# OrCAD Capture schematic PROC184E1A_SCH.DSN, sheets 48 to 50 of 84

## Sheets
48 51. JTAG MIPI60 CONN: size C; title: JTAG MIPI60 CONNECTOR; note: PROC184_SCH
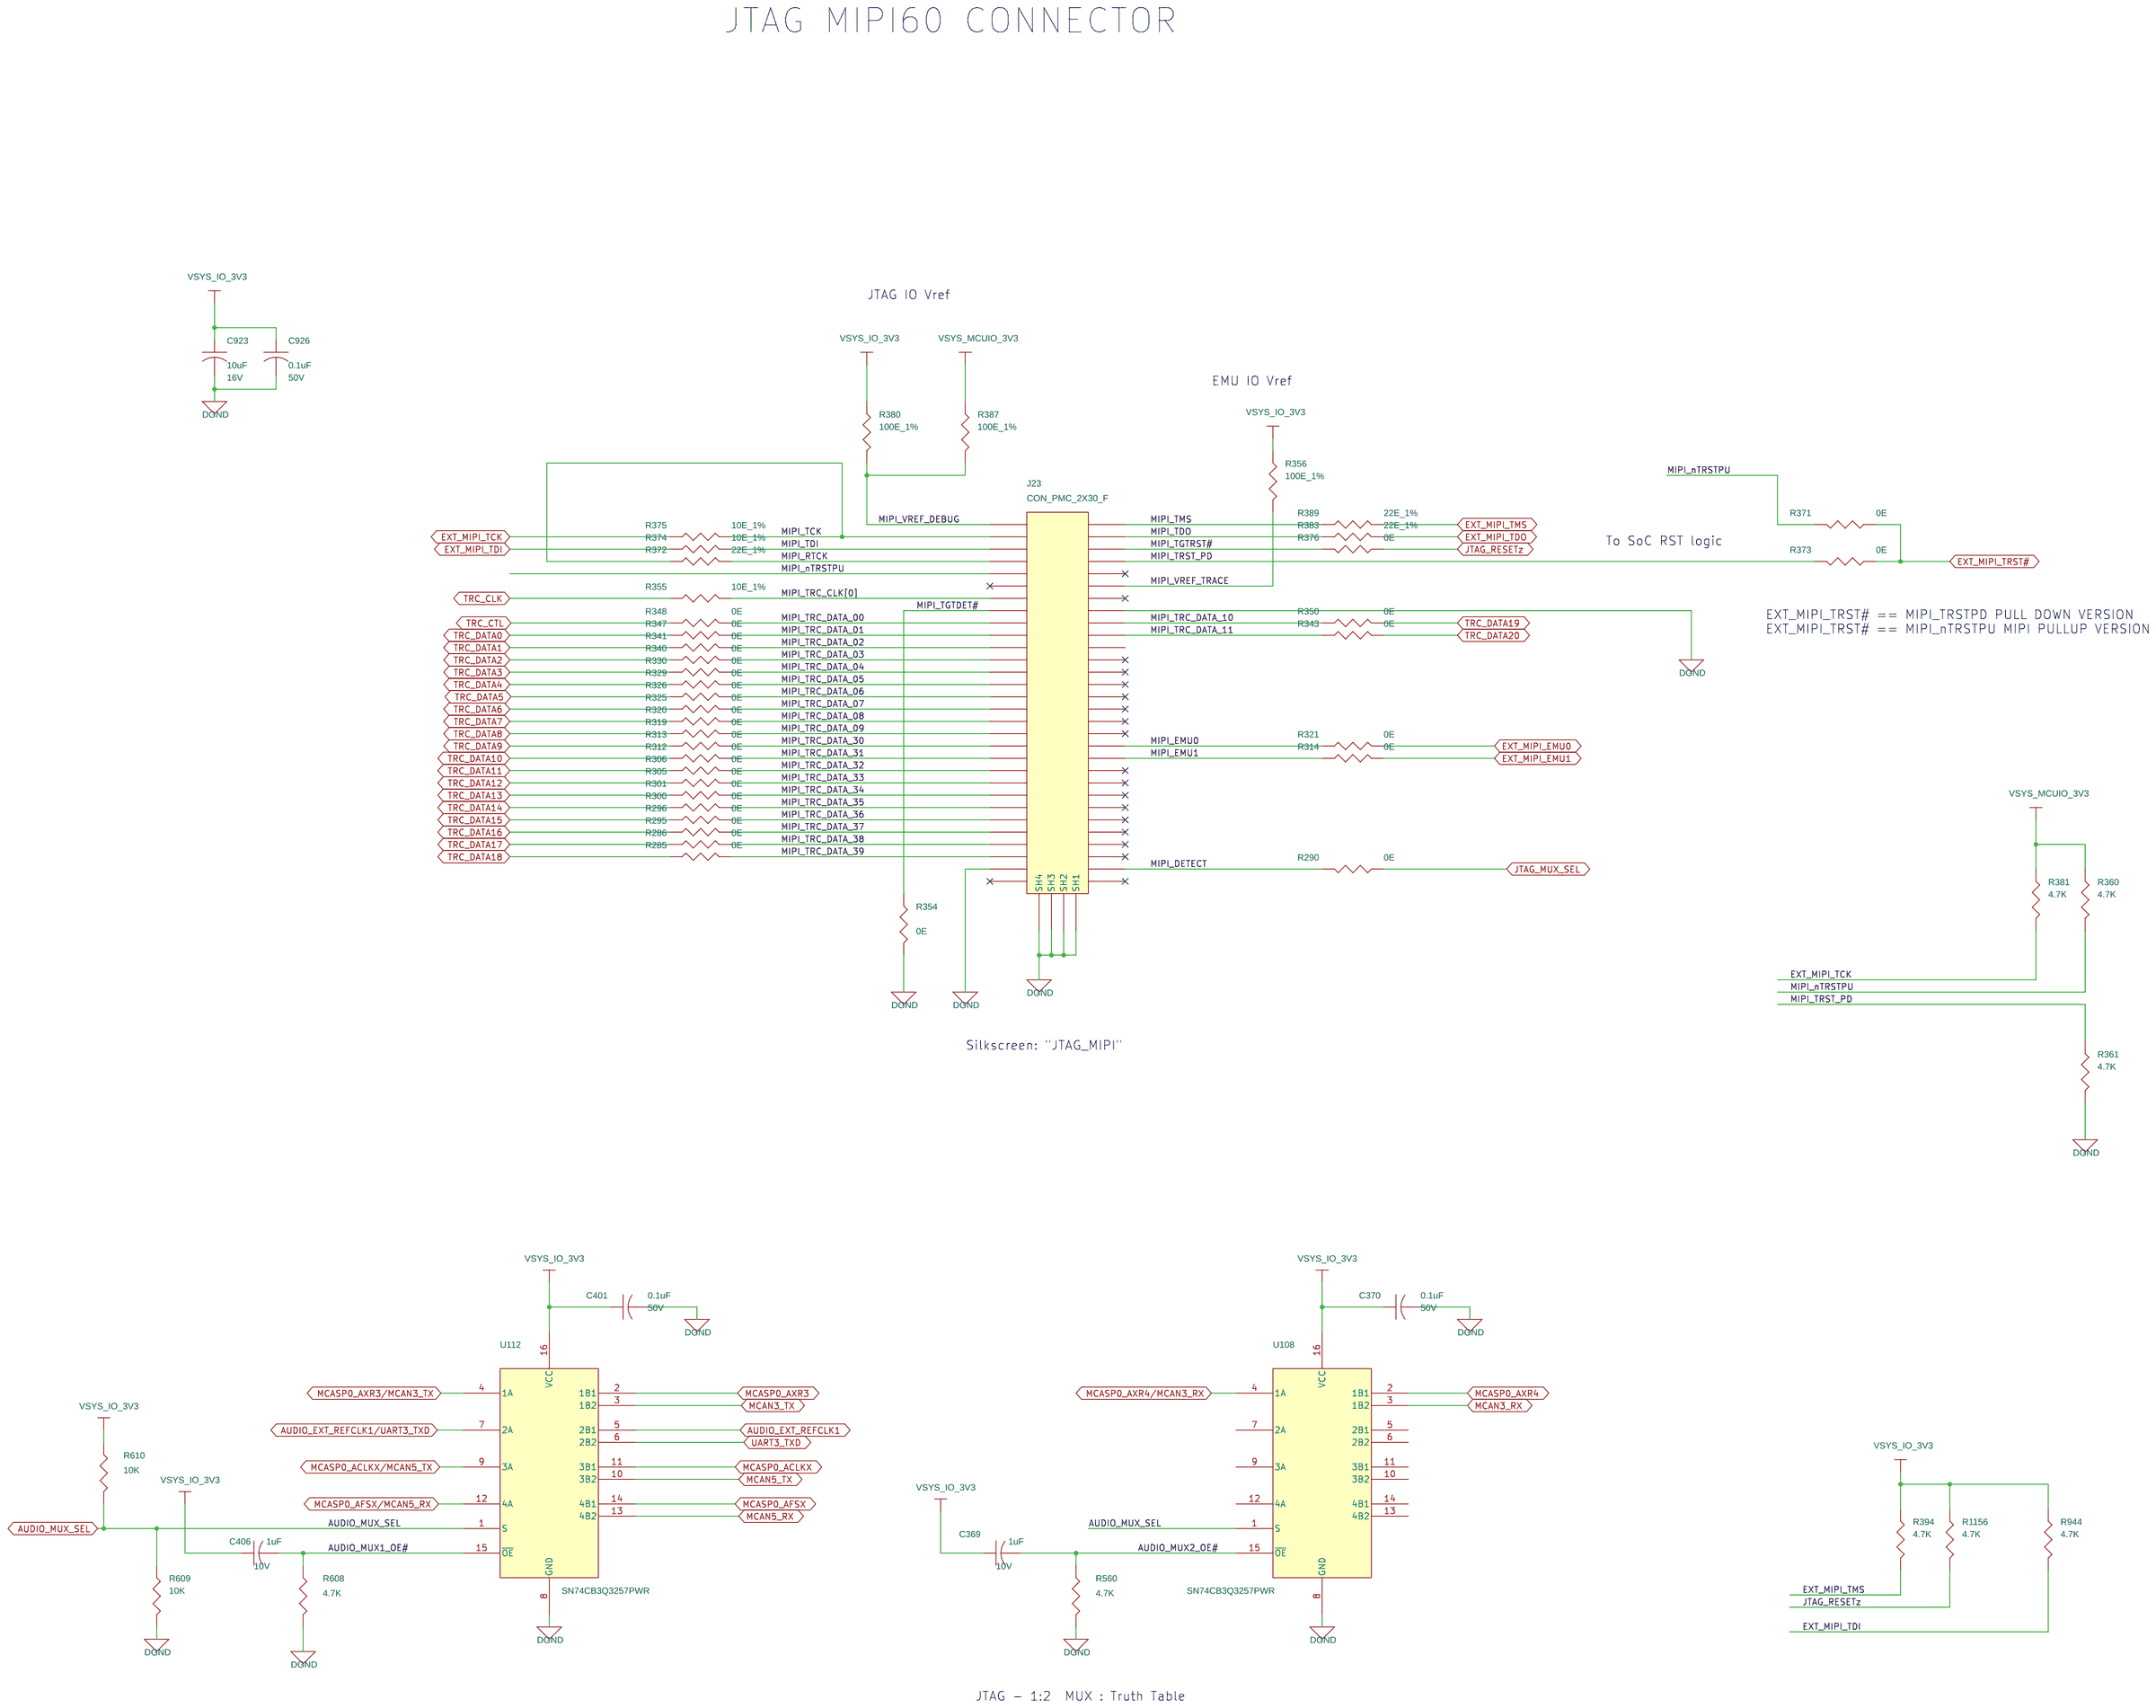
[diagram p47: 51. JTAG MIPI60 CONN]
49 53. CAN TRANSCEIVERS #1: size C; title: CAN TRANSCEIVERS #1; note: PROC184_SCH
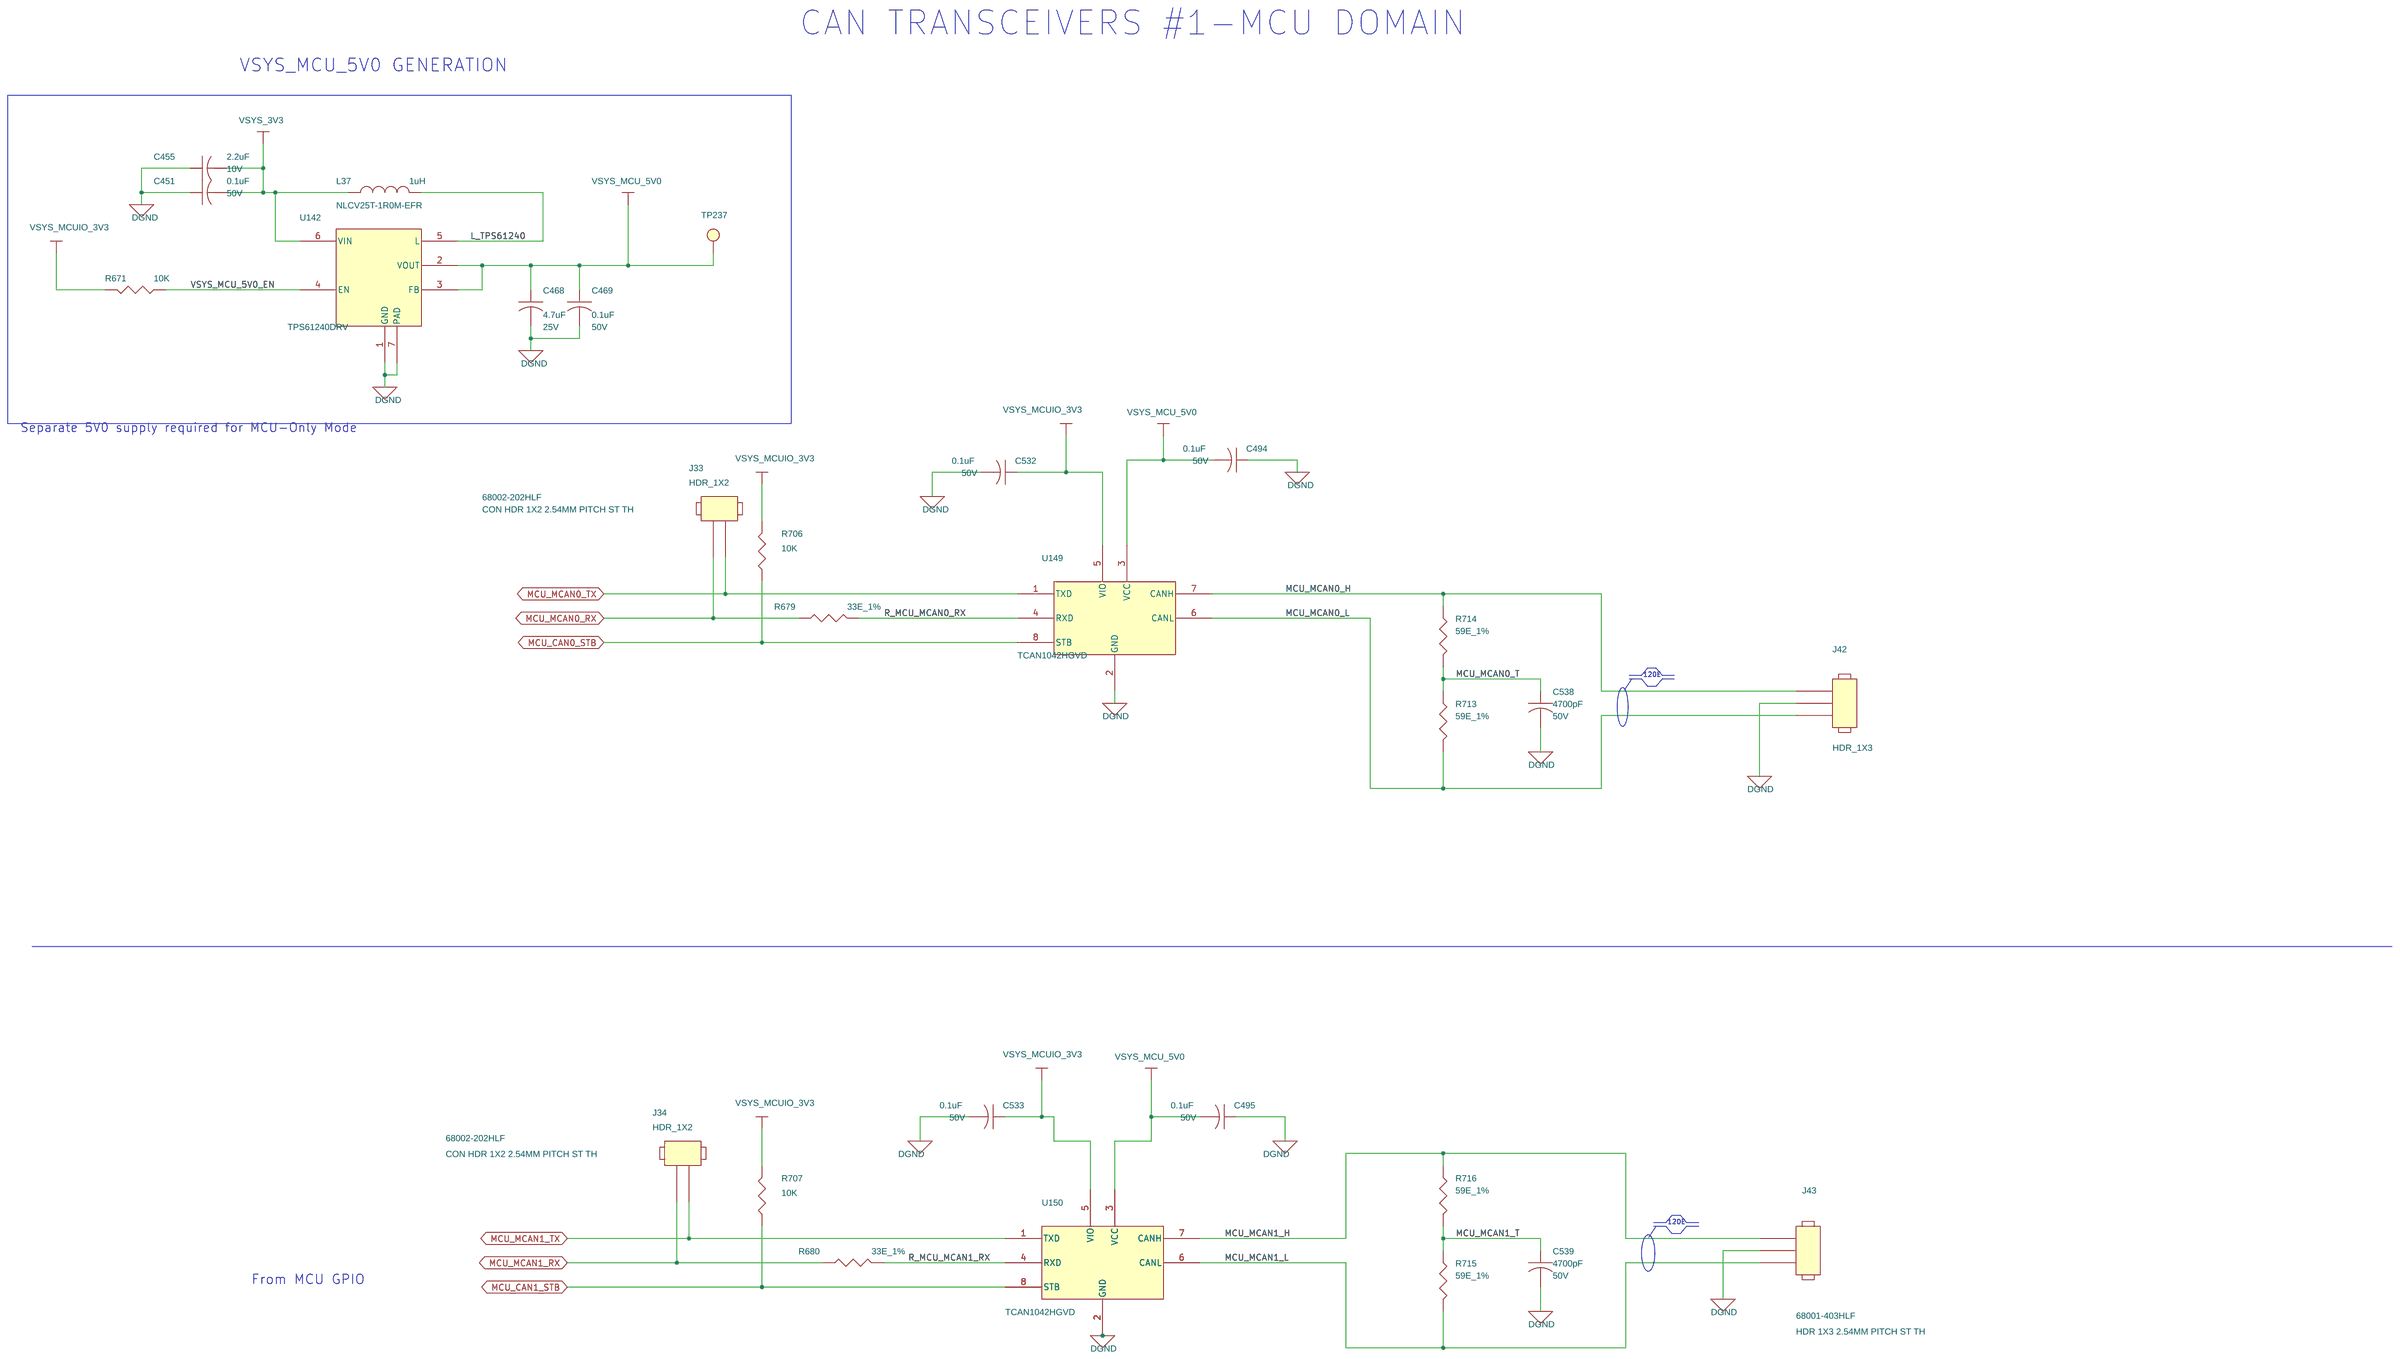
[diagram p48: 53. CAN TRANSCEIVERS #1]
50 54. CAN TRANSCEIVERS #2: size C; title: CAN TRANSCEIVER #2; note: PROC184_SCH
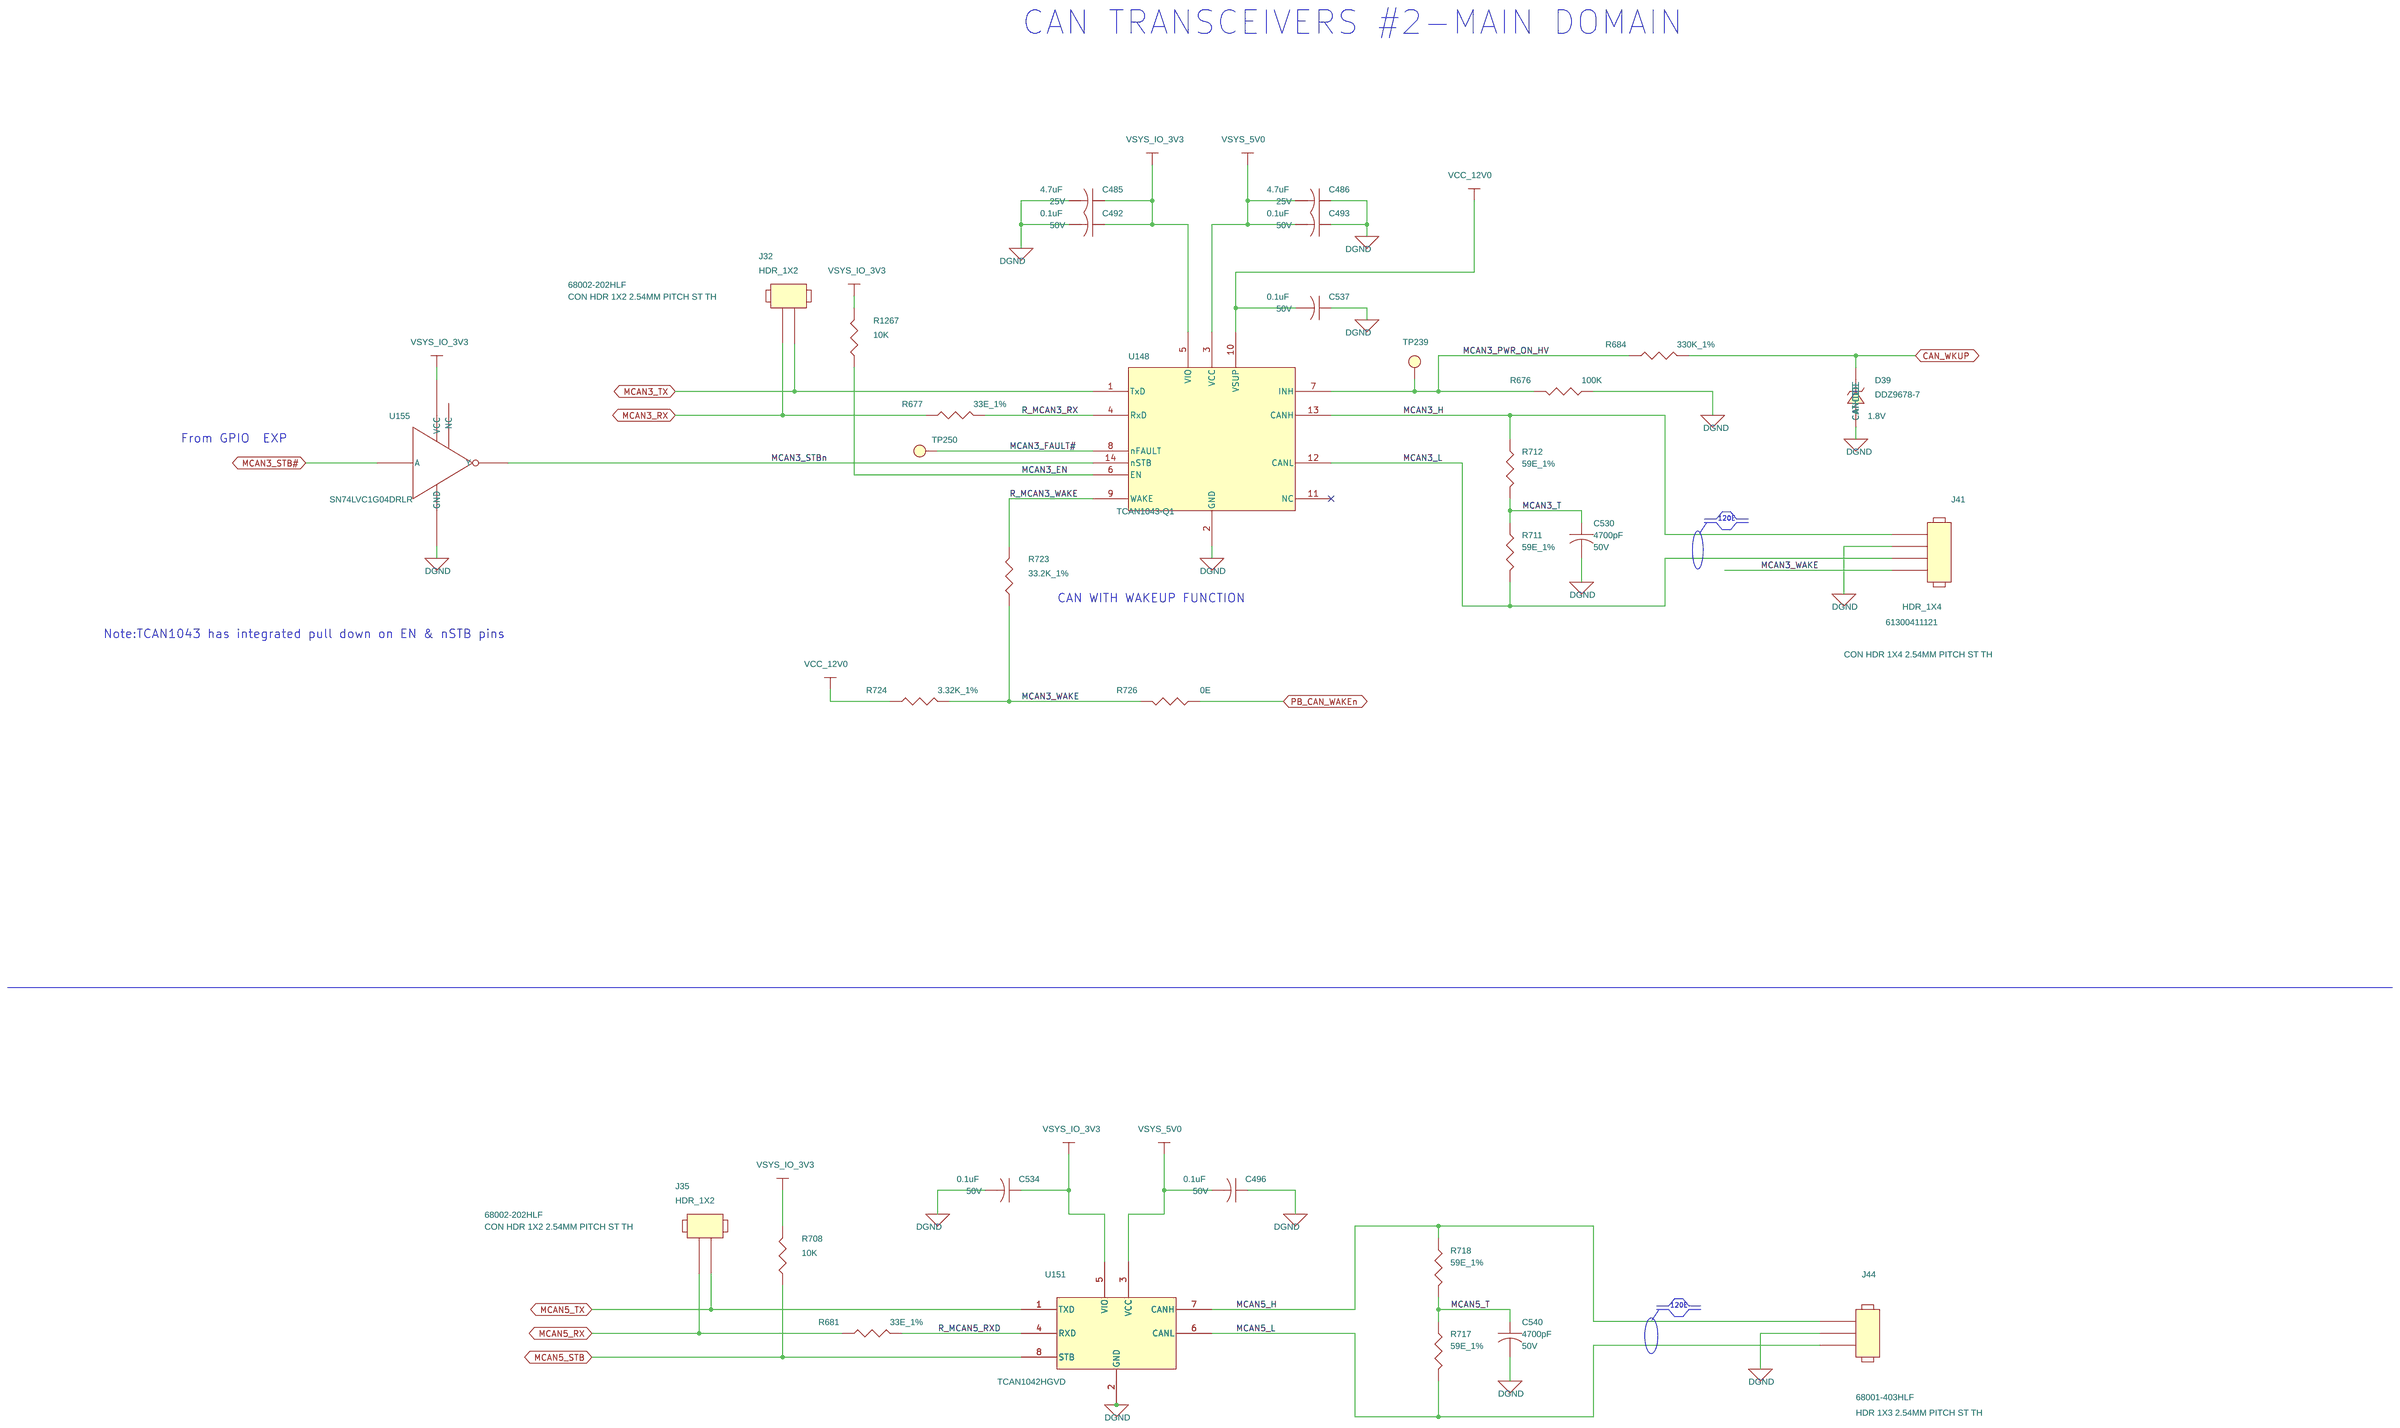
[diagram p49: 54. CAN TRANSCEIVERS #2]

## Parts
sheet 51. JTAG MIPI60 CONN
C369  1uF  [CAP0402_0-75]
C370  0.1uF  [CAP0402_0-75]
C401  0.1uF  [CAP0402_0-75]
C406  1uF  [CAP0402_0-75]
C923  10uF  [CAP0805_1-5]
C926  0.1uF  [CAP0402_0-75]
J23  CON_PMC_2X30_F  [CON_PMC2X30_QSH-030-01-D-A_S_S_S_3-3]
R285  0E  [RES0402_0-5]
R286  0E  [RES0402_0-5]
R290  0E  [RES0402_0-5]
R295  0E  [RES0402_0-5]
R296  0E  [RES0402_0-5]
R300  0E  [RES0402_0-5]
R301  0E  [RES0402_0-5]
R305  0E  [RES0402_0-5]
R306  0E  [RES0402_0-5]
R312  0E  [RES0402_0-5]
R313  0E  [RES0402_0-5]
R314  0E  [RES0402_0-5]
R319  0E  [RES0402_0-5]
R320  0E  [RES0402_0-5]
R321  0E  [RES0402_0-5]
R325  0E  [RES0402_0-5]
R326  0E  [RES0402_0-5]
R329  0E  [RES0402_0-5]
R330  0E  [RES0402_0-5]
R340  0E  [RES0402_0-5]
R341  0E  [RES0402_0-5]
R343  0E  [RES0402_0-5]
R347  0E  [RES0402_0-5]
R348  0E  [RES0402_0-5]
R350  0E  [RES0402_0-5]
R354  0E  [RES0402_0-5]
R355  10E_1%  [RES0402_0-5]
R356  100E_1%  [RES0402_0-5]
R360  4.7K  [RES0402_0-5]
R361  4.7K  [RES0402_0-5]
R371  0E  [RES0402_0-5]
R372  22E_1%  [RES0402_0-5]
R373  0E  [RES0402_0-5]
R374  10E_1%  [RES0402_0-5]
R375  10E_1%  [RES0402_0-5]
R376  0E  [RES0402_0-5]
R380  100E_1%  [RES0402_0-5]
R381  4.7K  [RES0402_0-5]
R383  22E_1%  [RES0402_0-5]
R387  100E_1%  [RES0402_0-5]
R389  22E_1%  [RES0402_0-5]
R394  4.7K  [RES0402_0-5]
R560  4.7K  [RES0402_0-5]
R608  4.7K  [RES0402_0-5]
R609  10K  [RES0402_0-5]
R610  10K  [RES0402_0-5]
R944  4.7K  [RES0402_0-5]
R1156  4.7K  [RES0402_0-5]
U108  SN74CB3Q3257PWR  [TSSOP16_25-59_205X180]
U112  SN74CB3Q3257PWR  [TSSOP16_25-59_205X180]
sheet 53. CAN TRANSCEIVERS #1
C451  0.1uF  [CAP0402_0-75]
C455  2.2uF  [CAP0402_0-75]
C468  4.7uF  [CAP0603_1]
C469  0.1uF  [CAP0402_0-75]
C494  0.1uF  [CAP0402_0-75]
C495  0.1uF  [CAP0402_0-75]
C532  0.1uF  [CAP0402_0-75]
C533  0.1uF  [CAP0402_0-75]
C538  4700pF  [CAP0402_0-75]
C539  4700pF  [CAP0402_0-75]
J33  HDR_1X2  [HDR_1X2_68002-202_S_T_8-6]
J34  HDR_1X2  [HDR_1X2_68002-202_S_T_8-6]
J42  HDR_1X3  [HDR_3X1_100_S_T]
J43  HDR_1X3  [HDR_3X1_100_S_T]
L37  1uH  [IND_NLCV25T-EFR_110X80_SMD_1-9]
R671  10K  [RES0402_0-5]
R679  33E_1%  [RES0402_0-5]
R680  33E_1%  [RES0402_0-5]
R706  10K  [RES0402_0-5]
R707  10K  [RES0402_0-5]
R713  59E_1%  [RES0402_0-5]
R714  59E_1%  [RES0402_0-5]
R715  59E_1%  [RES0402_0-5]
R716  59E_1%  [RES0402_0-5]
TP237  TP30_SMD  [TP30_SMD]
U142  TPS61240DRV  [SON6_25-59_85X85]
U149  TCAN1042HGVD  [SOIC8_1-8]
U150  TCAN1042HGVD  [SOIC8_1-8]
sheet 54. CAN TRANSCEIVERS #2
C485  4.7uF  [CAP0603_1]
C486  4.7uF  [CAP0603_1]
C492  0.1uF  [CAP0402_0-75]
C493  0.1uF  [CAP0402_0-75]
C496  0.1uF  [CAP0402_0-75]
C530  4700pF  [CAP0402_0-75]
C534  0.1uF  [CAP0402_0-75]
C537  0.1uF  [CAP0402_0-75]
C540  4700pF  [CAP0402_0-75]
D39  DDZ9678-7  [DIO_SOD123_1-5]
J32  HDR_1X2  [HDR_1X2_68002-202_S_T_8-6]
J35  HDR_1X2  [HDR_1X2_68002-202_S_T_8-6]
J41  HDR_1X4  [HDR_1X4_61300411121_S_T_8-6]
J44  HDR_1X3  [HDR_3X1_100_S_T]
R676  100K  [RES0402_0-5]
R677  33E_1%  [RES0402_0-5]
R681  33E_1%  [RES0402_0-5]
R684  330K_1%  [RES0402_0-5]
R708  10K  [RES0402_0-5]
R711  59E_1%  [RES0402_0-5]
R712  59E_1%  [RES0402_0-5]
R717  59E_1%  [RES0402_0-5]
R718  59E_1%  [RES0402_0-5]
R723  33.2K_1%  [RES0402_0-5]
R724  3.32K_1%  [RES0402_0-5]
R726  0E  [RES0402_0-5]
R1267  10K  [RES0402_0-5]
TP239  TP30_SMD  [TP30_SMD]
TP250  TP30_SMD  [TP30_SMD]
U148  TCAN1043-Q1  [SOIC14_1-8]
U151  TCAN1042HGVD  [SOIC8_1-8]
U155  SN74LVC1G04DRLR  [SOT553-5]

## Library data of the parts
C369 C406 = CAP: CAP CERAMIC 1uF 10V 10% X7S AUTO 0402; Automotive Alternate_mfr_name: TAIYO YUDEN; Automotive Alternate_mfr_part_number: EMK105BJ105KVHF; Chkd/date: MANIRAJA/100918; Crtd /date: ALVY/100918; Custom_Duty: 15%; Customs_HS_Code: 85322990; Direct Alternate_mfr_name: YAGEO AMERICA; Direct Alternate_mfr_part_number: CC0402KRX5R7BB105; Distributor_name: DIGIKEY; Distributor_part_number: 490-13409-1-ND; Footprint Path: Y:\MIS_DATABASE\Library\ALTIUM_TOOL\PCB_FOOTPRINTS\Altium_Footprint_Lib.PcbLib; Height: 0.70MM; Library Path: Y:\MIS_DATABASE\Library\ALTIUM_TOOL\SCHEMATICS_PARTS\MS_DISCRETE_Library.schlib; Manufacturer: TDK CORPORATION; Mfr_name: MURATA; Mfr_part_number: GCM155C71A105KE38D; Mistral Part No: 120018090021-R; Package: 0402; Part_type: CAPACITORS\CERAMIC; Project: SMART-M_SCRIPTALK_PB; RoHS: RoHS; Temperature: -55°C+125°C; Tolerance: 10%; Voltage: 10V; Wattage: NA; Weight: 6mg; Datasheet: Y:\MIS_DATABASE\DATASHEETS\CAPACITORS\MURATA-GCM-SER.PDF
C370 C401 C451 C469 C492-C496 C532-C534 C537 C926 = CAP: CAP CERAMIC 0.1uF 50V 10% X7R 0402; Automotive Alternate_mfr_name: TDK; Automotive Alternate_mfr_part_number: CGA2B3X7R1H104K050BB; Chkd/date: MANIRAJA/261020; Crtd /date: ALVY/211020; Custom_Duty: 15%; Customs_HS_Code: 85322990; Direct Alternate_mfr_name: TDK; Direct Alternate_mfr_part_number: C1005X7R1H104K050BE; Distributor_name: DIGIKEY; Distributor_part_number: 490-10700-1-ND; Footprint Path: Y:\MIS_DATABASE\Library\ALTIUM_TOOL\PCB_FOOTPRINTS\Altium_Footprint_Lib.PcbLib; Height: 0.55MM; Library Path: Y:\MIS_DATABASE\Library\ALTIUM_TOOL\SCHEMATICS_PARTS\MS_DISCRETE_Library.schlib; Manufacturer: MURATA; Mfr_name: MURATA; Mfr_part_number: GRM155R71H104KE14D; Mistral Part No: 120011100014-R; Package: 0402; Part_type: CAPACITORS\CERAMIC; Project: J7_CP; RoHS: RoHS; Temperature: -55°C+125°C; Tolerance: 10%; Voltage: 50V; Wattage: NA; Weight: 3.1mg; Datasheet: Y:\MIS_DATABASE\DATASHEETS\CAPACITORS\GRM155R71H104KE14.PDF
C923 = CAP: CAP CERAMIC 10uF 16V 10% X5R 0805; Automotive Alternate_mfr_name: TDK; Automotive Alternate_mfr_part_number: CGA4J1X7S1C106K125AC; Chkd/date: SHREESHAIL/220506; Crtd /date: MAZHAR/150506; Custom_Duty: 15%; Customs_HS_Code: 85322990; Direct Alternate_mfr_name: TDK; Direct Alternate_mfr_part_number: C2012X7S1C106K125AC; Distributor_name: DIGIKEY; Distributor_part_number: 490-3886-1-ND; Footprint Path: Y:\MIS_DATABASE\Library\ALTIUM_TOOL\PCB_FOOTPRINTS\Altium_Footprint_Lib.PcbLib; Height: 1.35MM; Library Path: Y:\MIS_DATABASE\Library\ALTIUM_TOOL\SCHEMATICS_PARTS\MS_DISCRETE_Library.schlib; Manufacturer: MURATA; Mfr_name: MURATA; Mfr_part_number: GRM21BR61C106KE15L; Mistral Part No: 120009030205-R; Package: 0805; Part_type: CAPACITORS\CERAMIC; Project: VOCERA; RoHS: RoHS; Temperature: -55°C+85°C; Tolerance: 10%; Voltage: 16V; Wattage: NA; Weight: 9.5mg; Datasheet: Y:\MIS_DATABASE\DATASHEETS\CAPACITORS\MURATA-GXX-SER_NOV17.PDF
J23 = CON_PMC_30X2_F_4SH: CON PMC 2X30 0.50MM PITCH FEMALE ST SMD; Chkd/date: MANIRAJA/310818; Crtd /date: ALVY/310818; Custom_Duty: 24%; Customs_HS_Code: 85369090; Distributor_name: DIGIKEY; Distributor_part_number: SAM13215CT-ND; Footprint Path: Y:\MIS_DATABASE\Library\ALTIUM_TOOL\PCB_FOOTPRINTS\Altium_Footprint_Lib.PcbLib; Height: 3.25MM; Library Path: Y:\MIS_DATABASE\Library\ALTIUM_TOOL\SCHEMATICS_PARTS\MS_CONNECTOR_Library.schlib; Manufacturer: SAMTEC; Mfr_name: SAMTEC; Mfr_part_number: QSH-030-01-L-D-A-K-TR; Mistral Part No: 150018080018-R; Package: SMD; Part_type: CONNECTOR\PMC; Project: 77GHzFR; RoHS: RoHS; Temperature: -55°C+125°C; Tolerance: NA; Voltage: NA; Wattage: NA; Weight: NA; Datasheet: Y:\MIS_DATABASE\DATASHEETS\CONNECTORS\QSH.PDF
R285 R286 R290 R295 R296 R300 R301 R305 R306 R312-R314 R319-R321 R325 R326 R329 R330 R340 R341 R343 R347 R348 R350 R354 R373 R376 R726 = RESISTOR: RES 0E 1/10W JUMPER 0402; Chkd/date: VASANTHA/061216; Crtd /date: NAVEED/201014; Custom_Duty: 15%; Customs_HS_Code: 85332119; Distributor_name: DIGIKEY; Distributor_part_number: P0.0JCT-ND; Footprint Path: Y:\MIS_DATABASE\Library\ALTIUM_TOOL\PCB_FOOTPRINTS\Altium_Footprint_Lib.PcbLib; Height: 0.40MM; IBISSP_MODLES: VALUE REPEATING 2 TIME; Library Path: Y:\MIS_DATABASE\Library\ALTIUM_TOOL\SCHEMATICS_PARTS\MS_DISCRETE_Library.schlib; Manufacturer: PANASONIC-ECG; Mfr_name: PANASONIC-ECG; Mfr_part_number: ERJ-2GE0R00X; Mistral Part No: 110018030052-R; Package: 0402; Part_type: RESISTORS\FIXED; Project: AEGIS POM; RoHS: RoHS; Temperature: -55°C+155°C; Tolerance: NA; Voltage: NA; Wattage: 1/10W; Weight: 0.8mg; Datasheet: Y:\MIS_DATABASE\DATASHEETS\RESISTORS\PAN-ERJSER_NOV17.PDF
R355 R374 R375 = RESISTOR: RES 10E 1/10W 1% 0402; Chkd/date: VASANTHA/201216; Crtd /date: MAZHAR/120505; Custom_Duty: 15%; Customs_HS_Code: 85332119; Distributor_name: DIGIKEY; Distributor_part_number: P10.0LCT-ND; Footprint Path: Y:\MIS_DATABASE\Library\ALTIUM_TOOL\PCB_FOOTPRINTS\Altium_Footprint_Lib.PcbLib; Height: 0.40MM; Library Path: Y:\MIS_DATABASE\Library\ALTIUM_TOOL\SCHEMATICS_PARTS\MS_DISCRETE_Library.schlib; Manufacturer: PANASONIC-ECG; Mfr_name: PANASONIC-ECG; Mfr_part_number: ERJ-2RKF10R0X; Mistral Part No: 110009030203-R; Package: 0402; Part_type: RESISTORS\FIXED; Project: CTP02_REVA_BASE; RoHS: RoHS; Temperature: -55°C+155°C; Tolerance: 1%; Voltage: NA; Wattage: 1/10W; Weight: 0.8mg; Datasheet: Y:\MIS_DATABASE\DATASHEETS\RESISTORS\PAN-ERJSER_NOV17.PDF
R356 R380 R387 = RESISTOR: RES 100E 1/10W 1% 0402; Chkd/date: MANIRAJA/130617; Crtd /date: JEBRAN/040715; Custom_Duty: 15%; Customs_HS_Code: 85332119; Distributor_name: DIGIKEY; Distributor_part_number: P100LCT-ND; Footprint Path: Y:\MIS_DATABASE\Library\ALTIUM_TOOL\PCB_FOOTPRINTS\Altium_Footprint_Lib.PcbLib; Height: 0.40MM; Library Path: Y:\MIS_DATABASE\Library\ALTIUM_TOOL\SCHEMATICS_PARTS\MS_DISCRETE_Library.schlib; Manufacturer: PANASONIC-ECG; Mfr_name: PANASONIC-ECG; Mfr_part_number: ERJ-2RKF1000X; Mistral Part No: 110018020036-R; Package: 0402; Part_type: RESISTORS\FIXED; Project: CYPHY_FVB; RoHS: RoHS; Temperature: -55°C+155°C; Tolerance: 1%; Voltage: NA; Wattage: 1/10W; Weight: 0.8mg; Datasheet: Y:\MIS_DATABASE\DATASHEETS\RESISTORS\PAN-ERJSER_NOV17.PDF
R360 R361 R381 R394 R560 R608 R944 R1156 = RESISTOR: RES 4.7K 1/16W 5% 0402; Chkd/date: VASANTHA/130516; Crtd /date: VASANTHA/130516; Custom_Duty: 15%; Customs_HS_Code: 85332119; Distributor_name: DIGIKEY; Distributor_part_number: 311-4.7KJRCT-ND; Footprint Path: Y:\MIS_DATABASE\Library\ALTIUM_TOOL\PCB_FOOTPRINTS\Altium_Footprint_Lib.PcbLib; Height: 0.40MM; Library Path: Y:\MIS_DATABASE\Library\ALTIUM_TOOL\SCHEMATICS_PARTS\MS_DISCRETE_Library.schlib; Manufacturer: YAGEO AMERICA; Mfr_name: YAGEO AMERICA; Mfr_part_number: RC0402JR-074K7L; Mistral Part No: 110011060001-R; Package: 0402; Part_type: RESISTORS\FIXED; Project: TMDXCSK368; RoHS: RoHS; Temperature: -55°C+155°C; Tolerance: 5%; Voltage: NA; Wattage: 1/16W; Weight: 0.65mg; Datasheet: Y:\MIS_DATABASE\DATASHEETS\RESISTORS\RCXXXXL-SER_MAR18.PDF
R371 = RESISTOR: RES 0E 1/10W JUMPER 0402; Assembly_Instruction: DNI; Chkd/date: VASANTHA/061216; Crtd /date: NAVEED/201014; Custom_Duty: 15%; Customs_HS_Code: 85332119; Distributor_name: DIGIKEY; Distributor_part_number: P0.0JCT-ND; Footprint Path: Y:\MIS_DATABASE\Library\ALTIUM_TOOL\PCB_FOOTPRINTS\Altium_Footprint_Lib.PcbLib; Height: 0.40MM; IBISSP_MODLES: VALUE REPEATING 2 TIME; Library Path: Y:\MIS_DATABASE\Library\ALTIUM_TOOL\SCHEMATICS_PARTS\MS_DISCRETE_Library.schlib; Manufacturer: PANASONIC-ECG; Mfr_name: PANASONIC-ECG; Mfr_part_number: ERJ-2GE0R00X; Mistral Part No: 110018030052-R; Package: 0402; Part_type: RESISTORS\FIXED; Project: AEGIS POM; RoHS: RoHS; Temperature: -55°C+155°C; Tolerance: NA; Voltage: NA; Wattage: 1/10W; Weight: 0.8mg; Datasheet: Y:\MIS_DATABASE\DATASHEETS\RESISTORS\PAN-ERJSER_NOV17.PDF
R372 R383 R389 = RESISTOR: RES 22E 1/16W 1% 0402; Chkd/date: SUHAS/290910; Crtd /date: MAZHAR/090909; Cust_part_number: 4700-80047E; Custom_Duty: 15%; Customs_HS_Code: 85332119; Distributor_name: DIGIKEY; Distributor_part_number: 311-22.0LRCT-ND; Footprint Path: Y:\MIS_DATABASE\Library\ALTIUM_TOOL\PCB_FOOTPRINTS\Altium_Footprint_Lib.PcbLib; Height: 0.40MM; Library Path: Y:\MIS_DATABASE\Library\ALTIUM_TOOL\SCHEMATICS_PARTS\MS_DISCRETE_Library.schlib; Manufacturer: YAGEO AMERICA; Mfr_name: YAGEO AMERICA; Mfr_part_number: RC0402FR-0722RL; Mistral Part No: 110009090004-R; Package: 0402; Part_type: RESISTORS\FIXED; Project: VMEFMCD; RoHS: RoHS; Temperature: -55°C+155°C; Tolerance: 1%; Voltage: NA; Wattage: 1/16W; Weight: 0.65mg; Datasheet: Y:\MIS_DATABASE\DATASHEETS\RESISTORS\RCXXXXL-SER_MAR18.PDF
R609 = RESISTOR: RES 10K 1/16W 5% 0402; Assembly_Instruction: DNI; Chkd/date: VASANTHA/061216; Crtd /date: MAZHAR/230805; Custom_Duty: 15%; Customs_HS_Code: 85332119; Distributor_name: DIGIKEY; Distributor_part_number: 311-10KJRCT-ND; Footprint Path: Y:\MIS_DATABASE\Library\ALTIUM_TOOL\PCB_FOOTPRINTS\Altium_Footprint_Lib.PcbLib; Height: 0.40MM; Library Path: Y:\MIS_DATABASE\Library\ALTIUM_TOOL\SCHEMATICS_PARTS\MS_DISCRETE_Library.schlib; Manufacturer: YAGEO AMERICA; Mfr_name: YAGEO AMERICA; Mfr_part_number: RC0402JR-0710KL; Mistral Part No: 110011060021-R; Package: 0402; Part_type: RESISTORS\FIXED; Project: HSE; RoHS: RoHS; Temperature: -55°C+155°C; Tolerance: 5%; Voltage: NA; Wattage: 1/16W; Weight: 0.65mg; Datasheet: Y:\MIS_DATABASE\DATASHEETS\RESISTORS\RCXXXXL-SER_MAR18.PDF
R610 R671 R706-R708 R1267 = RESISTOR: RES 10K 1/16W 5% 0402; Chkd/date: VASANTHA/061216; Crtd /date: MAZHAR/230805; Custom_Duty: 15%; Customs_HS_Code: 85332119; Distributor_name: DIGIKEY; Distributor_part_number: 311-10KJRCT-ND; Footprint Path: Y:\MIS_DATABASE\Library\ALTIUM_TOOL\PCB_FOOTPRINTS\Altium_Footprint_Lib.PcbLib; Height: 0.40MM; Library Path: Y:\MIS_DATABASE\Library\ALTIUM_TOOL\SCHEMATICS_PARTS\MS_DISCRETE_Library.schlib; Manufacturer: YAGEO AMERICA; Mfr_name: YAGEO AMERICA; Mfr_part_number: RC0402JR-0710KL; Mistral Part No: 110011060021-R; Package: 0402; Part_type: RESISTORS\FIXED; Project: HSE; RoHS: RoHS; Temperature: -55°C+155°C; Tolerance: 5%; Voltage: NA; Wattage: 1/16W; Weight: 0.65mg; Datasheet: Y:\MIS_DATABASE\DATASHEETS\RESISTORS\RCXXXXL-SER_MAR18.PDF
U108 U112 = SN74CB3Q3257PWR_TSSOP16: IC 4BIT 1-OF-2 FET MULTIPLEXER/DEMULTIPLEXER TSSOP16; Chkd/date: SUHAS/251010; Crtd /date: USMAN/060109; Custom_Duty: 15%; Customs_HS_Code: 85423100; Distributor_name: DIGIKEY; Distributor_part_number: 296-19138-1-ND; Height: 1.20MM; Manufacturer: TEXAS INSTRUMENTS; Mfr_name: TEXAS INSTRUMENTS; Mistral Part No: 141009030117-R; Package: TSSOP16; Part_type: ICS\DIGITAL\COMBINATIONAL; Project: OMAP_EVM; RoHS: Sb/ Br FREE; Temperature: -40°C+85°C; Datasheet: Y:\MIS_DATABASE\DATASHEETS\ICS\DIGITAL\COMBINATIONAL\SN74CB3Q3257.PDF
C455 = CAP: CAP CERAMIC 2.2uF 10V 10% X5R 0402; Automotive Alternate_mfr_name: TAIYO YUDEN; Automotive Alternate_mfr_part_number: LMK105ABJ225MVHF; Chkd/date: MANIRAJA/251120; Crtd /date: ALVY/241120; Custom_Duty: 15%; Customs_HS_Code: 85322990; Direct Alternate_mfr_name: TDK; Direct Alternate_mfr_part_number: C1005X5R1A225K050BC; Distributor_name: MOUSER; Distributor_part_number: 81-GRM155R61A225K01D; Footprint Path: Y:\MIS_DATABASE\Library\ALTIUM_TOOL\PCB_FOOTPRINTS\Altium_Footprint_Lib.PcbLib; Height: 0.55MM; Library Path: Y:\MIS_DATABASE\Library\ALTIUM_TOOL\SCHEMATICS_PARTS\MS_DISCRETE_Library.schlib; Manufacturer: MURATA; Mfr_name: MURATA; Mfr_part_number: GRM155R61A225KE01D; Mistral Part No: 120011100038-R; Package: 0402; Part_type: CAPACITORS\CERAMIC; Project: PLCC_DIGITAL BRD PROTO; RoHS: RoHS; Temperature: -55°C+85°C; Tolerance: 10%; Voltage: 10V; Wattage: NA; Weight: 1.6mg; Datasheet: Y:\MIS_DATABASE\DATASHEETS\CAPACITORS\MURATA-GXX-SER_NOV17.PDF
C468 C485 C486 = CAP: CAP CERAMIC 4.7uF 25V 10% X6S 0603; Chkd/date: MANIRAJA/241018; Crtd /date: ALVY/241018; Custom_Duty: 15%; Customs_HS_Code: 85322990; Direct Alternate_mfr_name: MURATA; Direct Alternate_mfr_part_number: GRM188C81E475ME11D; Distributor_name: DIGIKEY; Distributor_part_number: 490-7199-1-ND; Footprint Path: Y:\MIS_DATABASE\Library\ALTIUM_TOOL\PCB_FOOTPRINTS\Altium_Footprint_Lib.PcbLib; Height: 1.00MM; Library Path: Y:\MIS_DATABASE\Library\ALTIUM_TOOL\SCHEMATICS_PARTS\MS_DISCRETE_Library.schlib; Manufacturer: MURATA; Mfr_name: MURATA; Mfr_part_number: GRM188C81E475KE11D; Mistral Part No: 120018100056-R; Package: 0603; Part_type: CAPACITORS\CERAMIC; Project: TI_J7ES_EVM_CP; RoHS: RoHS; Temperature: -55°C+105°C; Tolerance: 10%; Voltage: 25V; Wattage: NA; Weight: 6.3mg; Datasheet: Y:\MIS_DATABASE\DATASHEETS\CAPACITORS\GRM188C81E475KE11D.PDF
C530 C538-C540 = CAP: CAP CERAMIC 4700pF 50V 5% X7R 0402; Automotive Alternate_mfr_name: TDK; Automotive Alternate_mfr_part_number: CGA2B2X7R1H472K050BA; Chkd/date: MANIRAJA/070619; Crtd /date: MANIRAJA/070619; Custom_Duty: 15%; Customs_HS_Code: 85322990; Direct Alternate_mfr_name: SAMSUNG; Direct Alternate_mfr_part_number: CL05B472KB5NNNC; Distributor_name: DIGIKEY; Distributor_part_number: 478-5767-1-ND; Footprint Path: Y:\MIS_DATABASE\Library\ALTIUM_TOOL\PCB_FOOTPRINTS\Altium_Footprint_Lib.PcbLib; Height: 0.56MM; Library Path: Y:\MIS_DATABASE\Library\ALTIUM_TOOL\SCHEMATICS_PARTS\MS_DISCRETE_Library.schlib; Manufacturer: AVX CORPORATION; Mfr_name: AVX CORPORATION; Mfr_part_number: 04025C472JAT2A; Mistral Part No: 120013090022-R; Package: 0402; Part_type: CAPACITORS\CERAMIC; Project: J7ES_SOM_DUAL-LEO_PMIC; RoHS: RoHS; Temperature: -55°C+125°C; Tolerance: 5%; Voltage: 50V; Wattage: NA; Weight: 0.65mg; Datasheet: Y:\MIS_DATABASE\DATASHEETS\CAPACITORS\AVX_MLC.PDF
J32-J35 = HEADER_2X1: CON HDR 1X2 2.54MM PITCH ST TH; Chkd/date: MANIRAJA/190118; Crtd /date: ALVY/190118; Custom_Duty: 24%; Customs_HS_Code: 85369090; Distributor_name: DIGIKEY; Distributor_part_number: 68002-202HLF-ND; Height: 8.58MM; Manufacturer: AMPHENOL; Mfr_name: AMPHENOL; Mfr_part_number: 68002-202HLF; Mistral Part No: 150018010012-R; Package: THRU HOLE; Part_type: CONNECTOR\HEADERS; Project: TI_SVB_MAXWELL_DUT; RoHS: RoHS; Temperature: NA; Tolerance: NA; Voltage: NA; Wattage: NA; Weight: NA; Datasheet: Y:\MIS_DATABASE\DATASHEETS\CONNECTORS\68002.PDF
J42-J44 = HEADER_3X1: HDR 1X3 2.54MM PITCH ST TH; Chkd/date: VASANTHA/290616; Crtd /date: VASANTHA/290616; Custom_Duty: 15%; Customs_HS_Code: 85322990; Distributor_name: DIGIKEY; Distributor_part_number: 609-3471-ND; Height: 8.58MM; Manufacturer: FCI; Mfr_name: FCI; Mfr_part_number: 68001-403HLF; Mistral Part No: 150016060025-R; Package: THRU-HOLE; Part_type: CONNECTOR\HEADERS; Project: IKEYP; RoHS: RoHS; Temperature: -40°C+105°C; Tolerance: NA; Voltage: NA; Wattage: NA; Weight: NA; Datasheet: Y:\MIS_DATABASE\DATASHEETS\CONNECTORS\68000.PDF
L37 = INDUCTOR: IND POWER 1uH 1A 20% SMD; Automotive Alternate_mfr_name: TDK; Automotive Alternate_mfr_part_number: NLCV25T-1R0M-EFRD; Chkd/date: MANIRAJA/161118; Crtd /date: ALVY/161118; Custom_Duty: 24%; Customs_HS_Code: 85369090; Direct Alternate_mfr_name: TDK; Direct Alternate_mfr_part_number: NLCV25T-1R0M-EFR; Distributor_name: DIGIKEY; Distributor_part_number: 445-17087-1-ND; Footprint Path: Y:\MIS_DATABASE\Library\ALTIUM_TOOL\PCB_FOOTPRINTS\Altium_Footprint_Lib.PcbLib; Height: 1.90MM; Library Path: Y:\MIS_DATABASE\Library\ALTIUM_TOOL\SCHEMATICS_PARTS\MS_DISCRETE_Library.schlib; Manufacturer: TDK CORPORATION; Mfr_name: TDK CORPORATION; Mfr_part_number: NLCV25T-1R0M-EFR; Mistral Part No: 130018110021-R; Package: SMD; Project: TI_J7ES_EVM_CP; RoHS: RoHS; Temperature: -40°C+125°C; Tolerance: 20%; Voltage: NA; Wattage: NA; Weight: 25mg; Datasheet: Y:\MIS_DATABASE\DATASHEETS\DISCRETES\INDUCTORS\NLCV25T-EFR.PDF
R677 R679-R681 = RESISTOR: RES 33E 1/10W 1% 0402; Chkd/date: VASANTHA/061216; Crtd /date: JEBRAN/171114; Custom_Duty: 15%; Customs_HS_Code: 85332119; Distributor_name: DIGIKEY; Distributor_part_number: P33.0LCT-ND; Footprint Path: Y:\MIS_DATABASE\Library\ALTIUM_TOOL\PCB_FOOTPRINTS\Altium_Footprint_Lib.PcbLib; Height: 0.40MM; Library Path: Y:\MIS_DATABASE\Library\ALTIUM_TOOL\SCHEMATICS_PARTS\MS_DISCRETE_Library.schlib; Manufacturer: PANASONIC-ECG; Mfr_name: PANASONIC-ECG; Mfr_part_number: ERJ-2RKF33R0X; Mistral Part No: 110014110006-R; Package: 0402; Part_type: RESISTORS\FIXED; Project: ZK BIOMETRIC; RoHS: RoHS; Temperature: -55°C+155°C; Tolerance: 1%; Voltage: NA; Wattage: 1/10W; Weight: 0.8mg; Datasheet: Y:\MIS_DATABASE\DATASHEETS\RESISTORS\PAN-ERJSER_NOV17.PDF
R711-R718 = RESISTOR: RES 59E 1/10W 1% 0402; Chkd/date: MAZHAR/151208; Crtd /date: USMAN/031208; Custom_Duty: 15%; Customs_HS_Code: 85332119; Distributor_name: DIGIKEY; Distributor_part_number: P59.0LCT-ND; Footprint Path: Y:\MIS_DATABASE\Library\ALTIUM_TOOL\PCB_FOOTPRINTS\Altium_Footprint_Lib.PcbLib; Height: 0.40MM; Library Path: Y:\MIS_DATABASE\Library\ALTIUM_TOOL\SCHEMATICS_PARTS\MS_DISCRETE_Library.schlib; Manufacturer: PANASONIC-ECG; Mfr_name: PANASONIC-ECG; Mfr_part_number: ERJ-2RKF59R0X; Mistral Part No: 110009031010-R; Package: 0402; Part_type: RESISTORS\FIXED; Project: KHAN_HSST; RoHS: RoHS; Temperature: -55°C+155°C; Tolerance: 1%; Voltage: NA; Wattage: 1/10W; Weight: 0.8mg; Datasheet: Y:\MIS_DATABASE\DATASHEETS\RESISTORS\PAN-ERJSER_NOV17.PDF
TP237 TP239 TP250 = TESTPOINT: TESTPOINT CIR 30 SMD; Chkd/date: SHREESHAIL/171006; Crtd /date: MAZHAR/171006; Custom_Duty: NA; Customs_HS_Code: NA; Distributor_name: NA; Distributor_part_number: NA; Footprint Path: Y:\MIS_DATABASE\Library\ALTIUM_TOOL\PCB_FOOTPRINTS\Altium_Footprint_Lib.PcbLib; Height: NA; Library Path: Y:\MIS_DATABASE\Library\ALTIUM_TOOL\SCHEMATICS_PARTS\MS_DISCRETE_Library.schlib; MECHANICAL 3D STEP FILE: NA; Manufacturer: LOCAL; Mfr_name: LOCAL; Mistral Part No: 130009030930; Package: SMD; Project: BT MODULE_CSRBC04; RoHS: NA; Temperature: NA; Tolerance: NA; Voltage: NA; Wattage: NA; Weight: NA; Datasheet: NA
U142 = TPS61240DRV_SON6: IC CONV STEP-UP 400MA DC/DC SON6; Automotive Alternate_mfr_name: TEXAS INSTRUMENTS; Automotive Alternate_mfr_part_number: TPS61240IDRVRQ1; Chkd/date: SUHAS/211010; Crtd /date: MAZHAR/240909; Custom_Duty: 15%; Customs_HS_Code: 85423100; Distributor_name: DIGIKEY; Distributor_part_number: 296-24519-1-ND; Footprint Path: Y:\MIS_DATABASE\Library\ALTIUM_TOOL\PCB_FOOTPRINTS\Altium_Footprint_Lib.PcbLib; Height: 0.80MM; Library Path: Y:\MIS_DATABASE\Library\ALTIUM_TOOL\SCHEMATICS_PARTS\MS_MISCPOWER_Library.schlib; Manufacturer: TEXAS INSTRUMENTS; Mfr_name: TEXAS INSTRUMENTS; Mistral Part No: 142009090013-P; Package: SON6; Part_type: ICS\POWER\DC-DC CONVERTER; Project: GOLDEN-I; RoHS: Sb/ Br FREE; Temperature: -40°C+85°C; Tolerance: NA; Voltage: NA; Wattage: NA; Datasheet: Y:\MIS_DATABASE\DATASHEETS\ICS\POWER\TPS6124.PDF
U149 = TCAN1042HGVD_SOIC8: IC FAULT PROTECTED CAN TRANSCEIVER WITH CAN FD SOIC8; Chkd/date: MANIRAJA/030717; Crtd /date: MANIRAJA/030717; Custom_Duty: 15%; Customs_HS_Code: 85423100; Distributor_name: DIGIKEY; Distributor_part_number: 296-43979-5-ND; Footprint Path: Y:\MIS_DATABASE\Library\ALTIUM_TOOL\PCB_FOOTPRINTS\Altium_Footprint_Lib.PcbLib; Height: 1.75MM; Library Path: Y:\MIS_DATABASE\Library\ALTIUM_TOOL\SCHEMATICS_PARTS\MS_TELECOM_Library.schlib; Manufacturer: TEXAS INSTRUMENTS; Mfr_name: TEXAS INSTRUMENTS; Mistral Part No: 143017070001-R; Package: SOIC8; Part_type: ICS\TELECOM\TRANSCEIVER; Project: TI_SVB_CONTROLLER CARD; RoHS: RoHS; Temperature: -55°C+125°C; Tolerance: NA; Voltage: NA; Wattage: NA; Weight: 540mg; Datasheet: Y:\MIS_DATABASE\DATASHEETS\ICS\DIGITAL\BUSTRANSCEIVER\TCAN1042.PDF
U150 U151 = TCAN1042HGVD_SOIC8: IC FAULT PROTECTED CAN TRANSCEIVER WITH CAN FD SOIC8; Automotive Alternate_mfr_name: TEXAS INSTRUMENTS; Automotive Alternate_mfr_part_number: TCAN1042HGV-Q1; Chkd/date: MANIRAJA/030717; Crtd /date: MANIRAJA/030717; Custom_Duty: 15%; Customs_HS_Code: 85423100; Distributor_name: DIGIKEY; Distributor_part_number: 296-43979-5-ND; Footprint Path: Y:\MIS_DATABASE\Library\ALTIUM_TOOL\PCB_FOOTPRINTS\Altium_Footprint_Lib.PcbLib; Height: 1.75MM; Library Path: Y:\MIS_DATABASE\Library\ALTIUM_TOOL\SCHEMATICS_PARTS\MS_TELECOM_Library.schlib; Manufacturer: TEXAS INSTRUMENTS; Mfr_name: TEXAS INSTRUMENTS; Mistral Part No: 143017070001-R; Package: SOIC8; Part_type: ICS\TELECOM\TRANSCEIVER; Project: TI_SVB_CONTROLLER CARD; RoHS: RoHS; Temperature: -55°C+125°C; Tolerance: NA; Voltage: NA; Wattage: NA; Weight: 540mg; Datasheet: Y:\MIS_DATABASE\DATASHEETS\ICS\DIGITAL\BUSTRANSCEIVER\TCAN1042.PDF
D39 = DIODE_ZENER: DIODE ZENER 500mW 1.8V SOD123; Chkd/date: MANIRAJA/220818; Crtd /date: ALVY/220818; Custom_Duty: 15%; Customs_HS_Code: 85412900; Distributor_name: DIGIKEY; Distributor_part_number: DDZ9678DICT-ND; Footprint Path: Y:\MIS_DATABASE\Library\ALTIUM_TOOL\PCB_FOOTPRINTS\Altium_Footprint_Lib.PcbLib; Height: 1.45MM; Library Path: Y:\MIS_DATABASE\Library\ALTIUM_TOOL\SCHEMATICS_PARTS\MS_DISCRETE_Library.schlib; Manufacturer: DIODES INC; Mfr_name: DIODES INC; Mistral Part No: 130018080024-R; Package: SOD123; Part_type: DIODE\ZENER; Project: MYTHIC_PCIE_DB; RoHS: RoHS; Temperature: -65°C+150°C; Tolerance: NA; Voltage: 1.8V; Wattage: NA; Weight: 10mg; Datasheet: Y:\MIS_DATABASE\DATASHEETS\DISCRETES\DIODES\DDZ9XXX.PDF
J41 = HEADER_4X1: CON HDR 1X4 2.54MM PITCH ST TH; Chkd/date: MANIRAJA/210918; Crtd /date: ALVY/210918; Custom_Duty: 24%; Customs_HS_Code: 85369090; Distributor_name: DIGIKEY; Distributor_part_number: 732-5317-ND; Footprint Path: Y:\MIS_DATABASE\Library\ALTIUM_TOOL\PCB_FOOTPRINTS\Altium_Footprint_Lib.PcbLib; Height: 8.54MM; Library Path: Y:\MIS_DATABASE\Library\ALTIUM_TOOL\SCHEMATICS_PARTS\MS_CONNECTOR_Library.schlib; Manufacturer: WURTH ELECTRONICS INC; Mfr_name: WURTH ELECTRONICS INC; Mfr_part_number: 61300411121; Mistral Part No: 150018090038-R; Package: THRU-HOLE; Part_type: CONNECTOR\HEADERS; Project: TI_60GHz-AOP; RoHS: RoHS; Temperature: -40°C+105°C; Tolerance: NA; Voltage: NA; Wattage: NA; Weight: 210mg; Datasheet: Y:\MIS_DATABASE\DATASHEETS\CONNECTORS\6130XXX.PDF
R676 = RESISTOR: RES 100K 1/10W 5% 0402; Chkd/date: VASANTHA/291216; Crtd /date: GEETHA/190406; Custom_Duty: 15%; Customs_HS_Code: 85332119; Distributor_name: DIGIKEY; Distributor_part_number: P100KJCT-ND; Footprint Path: Y:\MIS_DATABASE\Library\ALTIUM_TOOL\PCB_FOOTPRINTS\Altium_Footprint_Lib.PcbLib; Height: 0.40MM; Library Path: Y:\MIS_DATABASE\Library\ALTIUM_TOOL\SCHEMATICS_PARTS\MS_DISCRETE_Library.schlib; Manufacturer: PANASONIC-ECG; Mfr_name: PANASONIC-ECG; Mfr_part_number: ERJ-2GEJ104X; Mistral Part No: 110009030177-R; Package: 0402; Part_type: RESISTORS\FIXED; Project: RED EYE; RoHS: RoHS; Temperature: -55°C+155°C; Tolerance: 5%; Voltage: NA; Wattage: 1/10W; Weight: 0.8mg; Datasheet: Y:\MIS_DATABASE\DATASHEETS\RESISTORS\PAN-ERJSER_NOV17.PDF
R684 = RESISTOR: RES 330K 1/16W 1% 0402; Chkd/date: MANIRAJA/230817; Crtd /date: MANIRAJA/230817; Custom_Duty: 15%; Customs_HS_Code: 85332119; Distributor_name: DIGIKEY; Distributor_part_number: 541-330KLCT-ND; Footprint Path: Y:\MIS_DATABASE\Library\ALTIUM_TOOL\PCB_FOOTPRINTS\Altium_Footprint_Lib.PcbLib; Height: 0.40MM; Library Path: Y:\MIS_DATABASE\Library\ALTIUM_TOOL\SCHEMATICS_PARTS\MS_DISCRETE_Library.schlib; Manufacturer: VISHAY; Mfr_name: VISHAY; Mfr_part_number: CRCW0402330KFKED; Mistral Part No: 110017080024-R; Package: 0402; Part_type: RESISTORS\FIXED; Project: TI_MAXIE_CPB; RoHS: RoHS; Temperature: -55°C+155°C; Tolerance: 1%; Voltage: NA; Wattage: 1/16W; Weight: 0.65mg; Datasheet: Y:\MIS_DATABASE\DATASHEETS\RESISTORS\CRCW0603.PDF
R723 = RESISTOR: RES 33.2K 1/10W 1% 0402; Chkd/date: SHREESHAIL/310506; Crtd /date: GEETHA/290506; Custom_Duty: 15%; Customs_HS_Code: 85332119; Distributor_name: DIGIKEY; Distributor_part_number: P33.2KLTR-ND; Footprint Path: Y:\MIS_DATABASE\Library\ALTIUM_TOOL\PCB_FOOTPRINTS\Altium_Footprint_Lib.PcbLib; Height: 0.40MM; Library Path: Y:\MIS_DATABASE\Library\ALTIUM_TOOL\SCHEMATICS_PARTS\MS_DISCRETE_Library.schlib; Manufacturer: PANASONIC-ECG; Mfr_name: PANASONIC-ECG; Mfr_part_number: ERJ-2RKF3322X; Mistral Part No: 110009030682-R; Package: 0402; Part_type: RESISTORS\FIXED; Project: VOCERA; RoHS: RoHS; Temperature: -55°C+155°C; Tolerance: 1%; Voltage: NA; Wattage: 1/10W; Weight: 0.8mg; Datasheet: Y:\MIS_DATABASE\DATASHEETS\RESISTORS\PAN-ERJSER_NOV17.PDF
R724 = RESISTOR: RES 3.32K 1/16W 1% 0402; Chkd/date: MAZHAR/130709; Crtd /date: USMAN/230808; Custom_Duty: 15%; Customs_HS_Code: 85332119; Distributor_name: DIGIKEY; Distributor_part_number: 541-3.32KLCT-ND; Footprint Path: Y:\MIS_DATABASE\Library\ALTIUM_TOOL\PCB_FOOTPRINTS\Altium_Footprint_Lib.PcbLib; Height: 0.40MM; Library Path: Y:\MIS_DATABASE\Library\ALTIUM_TOOL\SCHEMATICS_PARTS\MS_DISCRETE_Library.schlib; Manufacturer: VISHAY; Mfr_name: VISHAY; Mfr_part_number: CRCW04023K32FKED; Mistral Part No: 110009030620-R; Package: 0402; Part_type: RESISTORS\FIXED; Project: CPB; RoHS: RoHS; Temperature: -55°C+155°C; Tolerance: 1%; Voltage: NA; Wattage: 1/16W; Weight: 0.65mg; Datasheet: Y:\MIS_DATABASE\DATASHEETS\RESISTORS\CRCW0603.PDF
U148 = TCAN1043DQ1_SOIC14_TI: IC FAULT PROTECTED CAN TRANSCEIVER WITH CAN FD AND WAKE SOIC14; Chkd/date: MANIRAJA/190918; Crtd /date: MANIRAJA/190918; Custom_Duty: 15%; Customs_HS_Code: 85423100; Distributor_name: DIGIKEY; Distributor_part_number: 296-47918-ND; Footprint Path: Y:\MIS_DATABASE\Library\ALTIUM_TOOL\PCB_FOOTPRINTS\Altium_Footprint_Lib.PcbLib; Height: 1.75MM; Library Path: Y:\MIS_DATABASE\Library\ALTIUM_TOOL\SCHEMATICS_PARTS\MS_TELECOM_Library.schlib; Library Ref: TCAN1043DQ1_SOIC14; Manufacturer: TEXAS INSTRUMENTS; Mfr_name: TEXAS INSTRUMENTS; Mfr_part_number: TCAN1043DQ1; Mistral Part No: 143018090001-R; Package: SOIC14; Part_type: ICS\TELECOM\TRANSCEIVER; Project: TI_J7ES_EVM_CP; RoHS: RoHS; Temperature: -55°C+125°C; Tolerance: NA; Voltage: NA; Wattage: NA; Weight: 195.3mg; Datasheet: Y:\MIS_DATABASE\DATASHEETS\ICS\TELECOM\TCAN1043XX-Q1.PDF
U155 = SN74LVC1G04DRLR_SOT553-5: IC SINGLE INVERTER GATE SOT553-5; Chkd/date: MAZHAR/110208; Crtd /date: USMAN/110208; Custom_Duty: 15%; Customs_HS_Code: 85423100; Distributor_name: DIGIKEY; Distributor_part_number: 296-18008-1-ND; Height: 0.60MM; Manufacturer: TEXAS INSTRUMENTS; Mfr_name: TEXAS INSTRUMENTS; Mistral Part No: 141009030225-R; Part_type: ICS\DIGITAL\GATES; Project: SMART VIEW_IP CAMERA; RoHS: Sb/ Br FREE; Stock: nil; Datasheet: Y:\MIS_DATABASE\DATASHEETS\ICS\DIGITAL\GATES\SN74LVC1G04-1.PDF

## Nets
DGND: C370.2 C401.2 C451.1 C455.1 C468.2 C469.2 C485.2 C486.1 C492.2 C493.1 C494.1 C495.1 C496.1 C530.2 C532.2 C533.2 C534.2 C537.1 C538.2 C539.2 C540.2 C923.2 C926.2 D39.2(ANODE) J23.16 J23.57 J23.61(SH1) J23.62(SH2) J23.63(SH3) J23.64(SH4) J41.2 J42.2 J43.2 J44.2 R354.2 R361.2 R560.2 R608.2 R609.2 R676.1 U108.8(GND) U112.8(GND) U142.1(GND) U142.7(PAD) U148.2(GND) U149.2(GND) U150.2(GND) U151.2(GND) U155.3(GND) ; also on sheet 11 12 13 14 15 16 17 18 20 21 22 23 24 25 26 27 28 29 30 31 32 33 34 35 36 37 38 39 40 41 42 43 44 45 46 47 51 52 53 54 55 56 57 58 59 60 61 62 63 64 65 66 67 68 69 70 71 72 73 76 77 78 79 81 82 83 84
VCC_12V0: C537.2 R724.1 U148.10(VSUP) ; also on sheet 30 31 46 53 59 60 64 66 83
AUDIO_EXT_REFCLK1: U112.5(2B1) ; also on sheet 82
AUDIO_EXT_REFCLK1/UART3_TXD: U112.7(2A) ; also on sheet 20
AUDIO_MUX1_OE#: C406.2 R608.1 U112.15(~{OE})
AUDIO_MUX2_OE#: C369.2 R560.1 U108.15(~{OE})
AUDIO_MUX_SEL: R609.1 R610.2 U108.1(S) U112.1(S) ; also on sheet 38
CAN_WKUP: D39.1(CATHODE) R684.2 ; also on sheet 69
EXT_MIPI_EMU0: R321.2 ; also on sheet 22
EXT_MIPI_EMU1: R314.2 ; also on sheet 22
EXT_MIPI_TCK: R375.1 R381.2 ; also on sheet 22
EXT_MIPI_TDI: R374.1 R944.2 ; also on sheet 22
EXT_MIPI_TDO: R383.2 ; also on sheet 22
EXT_MIPI_TMS: R389.2 R394.2 ; also on sheet 22
EXT_MIPI_TRST#: R371.1 R373.1 ; also on sheet 22
JTAG_MUX_SEL: R290.1 ; also on sheet 22
JTAG_RESETz: R376.1 R1156.2 ; also on sheet 36
L_TPS61240: L37.2 U142.5(L)
MCAN3_EN: R1267.1 U148.6(EN)
MCAN3_FAULT#: TP250.1(TP) U148.8(nFAULT)
MCAN3_H: J41.1 R712.1 U148.13(CANH)
MCAN3_L: J41.3 R711.2 U148.12(CANL)
MCAN3_PWR_ON_HV: R676.2 R684.1 TP239.1(TP) U148.7(INH)
MCAN3_RX: J32.2 R677.1 U108.3(1B2)
MCAN3_STB#: U155.2(A) ; also on sheet 38
MCAN3_STBn: U148.14(nSTB) U155.4(Y)
MCAN3_T: C530.1 R711.1 R712.2
MCAN3_TX: J32.1 U112.3(1B2) U148.1(TxD)
MCAN3_WAKE: J41.4 R723.1 R724.2 R726.2
MCAN5_H: J44.1 R718.1 U151.7(CANH)
MCAN5_L: J44.3 R717.2 U151.6(CANL)
MCAN5_RX: J35.2 R681.1 U112.13(4B2)
MCAN5_STB: R708.1 U151.8(STB) ; also on sheet 38
MCAN5_T: C540.1 R717.1 R718.2
MCAN5_TX: J35.1 U112.10(3B2) U151.1(TXD)
MCASP0_ACLKX: U112.11(3B1) ; also on sheet 82
MCASP0_ACLKX/MCAN5_TX: U112.9(3A) ; also on sheet 20
MCASP0_AFSX: U112.14(4B1) ; also on sheet 82
MCASP0_AFSX/MCAN5_RX: U112.12(4A) ; also on sheet 20
MCASP0_AXR3: U112.2(1B1) ; also on sheet 82
MCASP0_AXR3/MCAN3_TX: U112.4(1A) ; also on sheet 20
MCASP0_AXR4: U108.2(1B1) ; also on sheet 82
MCASP0_AXR4/MCAN3_RX: U108.4(1A) ; also on sheet 20
MCU_CAN0_STB: R706.1 U149.8(STB) ; also on sheet 18
MCU_CAN1_STB: R707.1 U150.8(STB) ; also on sheet 18
MCU_MCAN0_H: J42.1 R714.1 U149.7(CANH)
MCU_MCAN0_L: J42.3 R713.2 U149.6(CANL)
MCU_MCAN0_RX: J33.2 R679.1 ; also on sheet 18
MCU_MCAN0_T: C538.1 R713.1 R714.2
MCU_MCAN0_TX: J33.1 U149.1(TXD) ; also on sheet 18
MCU_MCAN1_H: J43.1 R716.1 U150.7(CANH)
MCU_MCAN1_L: J43.3 R715.2 U150.6(CANL)
MCU_MCAN1_RX: J34.2 R680.1 ; also on sheet 18
MCU_MCAN1_T: C539.1 R715.1 R716.2
MCU_MCAN1_TX: J34.1 U150.1(TXD) ; also on sheet 18
MIPI_DETECT: J23.58 R290.2
MIPI_EMU0: J23.38 R321.1
MIPI_EMU1: J23.40 R314.1
MIPI_nTRSTPU: J23.9 R360.2 R371.2
MIPI_RTCK: J23.7 R372.2
MIPI_TCK: J23.3 R372.1 R375.2
MIPI_TDI: J23.5 R374.2
MIPI_TDO: J23.4 R383.1
MIPI_TGTDET#: J23.15 R354.1
MIPI_TGTRST#: J23.6 R376.2
MIPI_TMS: J23.2 R389.1
MIPI_TRC_CLK[0]: J23.13 R355.2
MIPI_TRC_DATA_00: J23.17 R348.2
MIPI_TRC_DATA_01: J23.19 R347.2
MIPI_TRC_DATA_02: J23.21 R341.2
MIPI_TRC_DATA_03: J23.23 R340.2
MIPI_TRC_DATA_04: J23.25 R330.2
MIPI_TRC_DATA_05: J23.27 R329.2
MIPI_TRC_DATA_06: J23.29 R326.2
MIPI_TRC_DATA_07: J23.31 R325.2
MIPI_TRC_DATA_08: J23.33 R320.2
MIPI_TRC_DATA_09: J23.35 R319.2
MIPI_TRC_DATA_10: J23.18 R350.1
MIPI_TRC_DATA_11: J23.20 R343.1
MIPI_TRC_DATA_30: J23.37 R313.2
MIPI_TRC_DATA_31: J23.39 R312.2
MIPI_TRC_DATA_32: J23.41 R306.2
MIPI_TRC_DATA_33: J23.43 R305.2
MIPI_TRC_DATA_34: J23.45 R301.2
MIPI_TRC_DATA_35: J23.47 R300.2
MIPI_TRC_DATA_36: J23.49 R296.2
MIPI_TRC_DATA_37: J23.51 R295.2
MIPI_TRC_DATA_38: J23.53 R286.2
MIPI_TRC_DATA_39: J23.55 R285.2
MIPI_TRST_PD: J23.8 R361.1 R373.2
MIPI_VREF_DEBUG: J23.1 R380.2 R387.2
MIPI_VREF_TRACE: J23.12 R356.2
PB_CAN_WAKEn: R726.1 ; also on sheet 35 69
R_MCAN3_RX: R677.2 U148.4(RxD)
R_MCAN3_WAKE: R723.2 U148.9(WAKE)
R_MCAN5_RXD: R681.2 U151.4(RXD)
R_MCU_MCAN0_RX: R679.2 U149.4(RXD)
R_MCU_MCAN1_RX: R680.2 U150.4(RXD)
TRC_CLK: R355.1 ; also on sheet 20
TRC_CTL: R348.1 ; also on sheet 20
TRC_DATA0: R347.1 ; also on sheet 20
TRC_DATA1: R341.1 ; also on sheet 20
TRC_DATA2: R340.1 ; also on sheet 20
TRC_DATA3: R330.1 ; also on sheet 20
TRC_DATA4: R329.1 ; also on sheet 20
TRC_DATA5: R326.1 ; also on sheet 20
TRC_DATA6: R325.1 ; also on sheet 20
TRC_DATA7: R320.1 ; also on sheet 20
TRC_DATA8: R319.1 ; also on sheet 20
TRC_DATA9: R313.1 ; also on sheet 20
TRC_DATA10: R312.1 ; also on sheet 20
TRC_DATA11: R306.1 ; also on sheet 20
TRC_DATA12: R305.1 ; also on sheet 20
TRC_DATA13: R301.1 ; also on sheet 20
TRC_DATA14: R300.1 ; also on sheet 20
TRC_DATA15: R296.1 ; also on sheet 20
TRC_DATA16: R295.1 ; also on sheet 20
TRC_DATA17: R286.1 ; also on sheet 20
TRC_DATA18: R285.1 ; also on sheet 20
TRC_DATA19: R350.2 ; also on sheet 20
TRC_DATA20: R343.2 ; also on sheet 20
UART3_TXD: U112.6(2B2) ; also on sheet 45
VSYS_3V3: C451.2 C455.2 L37.1 U142.6(VIN) ; also on sheet 22 23 35 36 40 47 62 63 65 66 67 68 69 73 75 76 77 78 79
VSYS_5V0: C486.2 C493.2 C496.2 U148.3(VCC) U151.3(VCC) ; also on sheet 20 30 31 52 59 65 68 72 81 82 83 84
VSYS_IO_3V3: C369.1 C370.1 C401.1 C406.1 C485.1 C492.1 C534.1 C923.1 C926.1 R356.1 R380.1 R394.1 R610.1 R708.2 R944.1 R1156.1 R1267.2 U108.16(VCC) U112.16(VCC) U148.5(VIO) U151.5(VIO) U155.5(VCC) ; also on sheet 18 20 22 24 29 30 31 32 33 35 36 37 38 40 41 42 43 45 46 51 53 56 57 58 59 60 61 65 66 68 75 81 82
VSYS_MCU_5V0: C468.1 C469.1 C494.2 C495.2 TP237.1(TP) U142.2(VOUT) U142.3(FB) U149.3(VCC) U150.3(VCC) ; also on sheet 68
VSYS_MCU_5V0_EN: R671.1 U142.4(EN)
VSYS_MCUIO_3V3: C532.1 C533.1 R360.1 R381.1 R387.1 R671.2 R706.2 R707.2 U149.5(VIO) U150.5(VIO) ; also on sheet 16 17 18 21 22 23 35 36 43 44 55 62 65 68 75

Not connected (* = marked no-connect by the designer): J23 10* 11* 14* 22 24* 26* 28* 30* 32* 34* 36* 42* 44* 46* 48* 50* 52* 54* 56* 59* 60*; U108 5(2B1) 6(2B2) 7(2A) 9(3A) 10(3B2) 11(3B1) 12(4A) 13(4B2) 14(4B1); U148 11(NC)*; U155 1(NC)

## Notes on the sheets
sheet 48
- JTAG MIPI60 CONNECTOR
- JTAG IO Vref
- EMU IO Vref
- To SoC RST logic
- EXT_MIPI_TRST# == MIPI_TRSTPD PULL DOWN VERSION
  EXT_MIPI_TRST# == MIPI_nTRSTPU MIPI PULLUP VERSION
- Silkscreen: "JTAG_MIPI"
- JTAG - 1:2  MUX : Truth Table
sheet 49
- CAN TRANSCEIVERS #1-MCU DOMAIN
- VSYS_MCU_5V0 GENERATION
- Separate 5V0 supply required for MCU-Only Mode
- 120E
- 120E
- From MCU GPIO
sheet 50
- CAN TRANSCEIVERS #2-MAIN DOMAIN
- From GPIO  EXP
- 120E
- CAN WITH WAKEUP FUNCTION
- Note:TCAN1043 has integrated pull down on EN & nSTB pins
- 120E
